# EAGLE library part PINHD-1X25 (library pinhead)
PIN HEADER
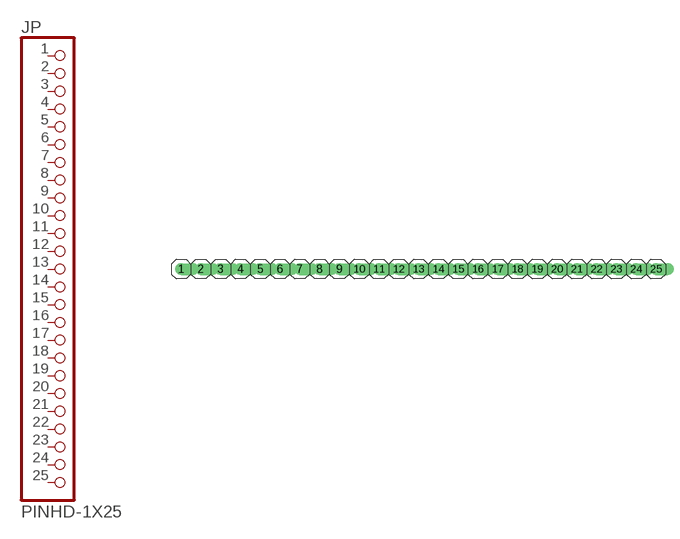
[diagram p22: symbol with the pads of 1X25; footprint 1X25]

Designator prefix JP

## PINHD-1X25  [1X25]
1  1  pas
2  2  pas
3  3  pas
4  4  pas
5  5  pas
6  6  pas
7  7  pas
8  8  pas
9  9  pas
10  10  pas
11  11  pas
12  12  pas
13  13  pas
14  14  pas
15  15  pas
16  16  pas
17  17  pas
18  18  pas
19  19  pas
20  20  pas
21  21  pas
22  22  pas
23  23  pas
24  24  pas
25  25  pas

## Footprint 1X25 (pad centres in mm)
PIN HEADER
drill 1.016 offset: 1 -29.21,0; 2 -26.67,0; 3 -24.13,0; 4 -21.59,0; 5 -19.05,0; 6 -16.51,0; 7 -13.97,0; 8 -11.43,0; 9 -8.89,0; 10 -6.35,0; 11 -3.81,0; 12 -1.27,0; 13 1.27,0; 14 3.81,0; 15 6.35,0; 16 8.89,0; 17 11.43,0; 18 13.97,0; 19 16.51,0; 20 19.05,0; 21 21.59,0; 22 24.13,0; 23 26.67,0; 24 29.21,0; 25 31.75,0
